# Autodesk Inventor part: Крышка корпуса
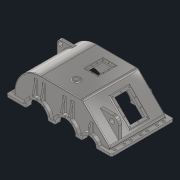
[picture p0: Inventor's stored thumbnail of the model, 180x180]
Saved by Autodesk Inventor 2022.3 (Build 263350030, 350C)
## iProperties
Created: 2022-08
Part Number: Крышка корпуса
Material: Сталь 40ХНМА
Document SubType Name: Modeling
Designer: Карташов
Density: 7.85 g/cm^3
Appearance: С умеренной полировкой
Author: Карташов
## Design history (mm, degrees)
sketch "Эскиз1"
  geometry: L1 (0, 0)-(0, 15); L2 (0, 15)-(30, 15); L3 (30, 15)-(30, 30); L4 (200, 200)-(450, 200); L5 (464.142, 194.142)-(624.142, 34.142); L6 (630, 20)-(630, 15); L7 (630, 15)-(660, 15); L8 (660, 15)-(660, 0); L9 (660, 0)-(0, 0); L10 (0, 0)-(660, 0); L11 (660, 0)-(660, 15); L12 (660, 15)-(0, 15); L13 (0, 15)-(0, 0); A1 r 170 centre (200, 30) between (200, 200) and (30, 30); A2 r 20 centre (450, 180) between (464.142, 194.142) and (450, 200); A3 r 20 centre (610, 20) between (630, 20) and (624.142, 34.142); 4 further points
  constraints: 26 end point, 6 point on circle, 6 tangent, 4 parallel, 3 centre point, 3 horizontal, 3 perpendicular, 2 vertical
  dimensions: "d0" = 200 distance between parallel lines of L4 L9; "d1" = 660 distance of L8.end L1.start; "d2" = 30 distance of L6.end L7.end; "d3" = 15 distance of L7.end L8.end; "d4" = 20 radius of A3; "d5" = 20 radius of A2; "d6" = 30 distance of L1.end L2.end; "d7" = 15 distance of L1.start L1.end; "d8" = 170 radius of A1; "d9" = 45 deg angle of L4 L5; "d10" = 5 distance of L6.start L6.end
extrude "Выдавливание1" new body sketch "Эскиз1" stored distance "d11" = 350; taper "d12" = 0 deg
extrude "Выдавливание2" join sketch "Эскиз1" stored distance "d13" = 390; taper "d14" = 0 deg
feature "Оболочка1" dims "d16" = 15
fillet "Сопряжение2" dims "d17" = 3
sketch "Эскиз2"
  geometry: L1 (660, 15)-(0, 15) reference; L2 (0, 15)-(0, 0) reference; L3 (0, 0)-(660, 0) reference; L4 (660, 0)-(660, 15) reference; L5 (30, 30)-(30, 18) reference; L6 (27, 15)-(630, 15) reference; L7 (630, 15)-(630, 20) reference; L8 (624.142, 34.142)-(464.142, 194.142) reference; L9 (450, 200)-(200, 200) reference; L10 (615, 0)-(45, 0) reference; C1 r 70 at (192, 0); C2 r 65 at (370, 0); C3 r 45 at (520, 0); A1 r 3 centre (27, 18) between (27, 15) and (30, 18) reference; A2 r 20 centre (610, 20) between (630, 20) and (624.142, 34.142) reference; A3 r 20 centre (450, 180) between (464.142, 194.142) and (450, 200) reference; A4 r 170 centre (200, 30) between (200, 200) and (30, 30) reference; 2 further points
  constraints: 3 centre point, 3 point on line, 1 midpoint
  dimensions: "d18" = 140 diameter of C1; "d19" = 130 diameter of C2; "d20" = 90 diameter of C3; "d21" = 192 horizontal distance of point (0, 7.5) C1.centre; "d22" = 178 distance of C2.centre C1.centre; "d23" = 150 distance of C3.centre C2.centre
extrude "Выдавливание3" cut sketch "Эскиз2" distance "d24" = 264.25; taper "d25" = 0 deg
sketch "Эскиз3"
  geometry: L1 (0, 15)-(-660, 15) reference; L2 (-660, 15)-(-660, 0) reference; L3 (-660, 0)-(0, 0) reference; L4 (0, 0)-(0, 15) reference; L5 (-615, 0)-(-45, 0) reference; L6 (-435, 0)-(-475, 0) reference; L7 (-262, 0)-(-305, 0) reference; L8 (-45, 0)-(-122, 0) reference; L9 (-45, 30)-(-45, 0) reference; L10 (-450, 185)-(-200, 185) reference; L11 (-613.536, 23.536)-(-453.536, 183.536) reference; L12 (-615, 0)-(-615, 20) reference; L13 (-565, 0)-(-615, 0) reference; C1 r 75 at (-192, 0); C2 r 55 at (-370, 0); C3 r 45 at (-520, 0); A1 r 45 centre (-520, 0) between (-475, 0) and (-565, 0) reference; A2 r 65 centre (-370, 0) between (-305, 0) and (-435, 0) reference; A3 r 70 centre (-192, 0) between (-122, 0) and (-262, 0) reference; A4 r 155 centre (-200, 30) between (-45, 30) and (-200, 185) reference; A5 r 5 centre (-450, 180) between (-450, 185) and (-453.536, 183.536) reference; A6 r 5 centre (-610, 20) between (-613.536, 23.536) and (-615, 20) reference; 1 further point
  constraints: 3 centre point, 3 coincident, 3 point on line, 2 other
  dimensions: "d26" = 150 diameter of C1; "d27" = 110 diameter of C2; "d28" = 90 diameter of C3
extrude "Выдавливание4" cut sketch "Эскиз3" distance "d29" = 139.5; taper "d30" = 0 deg
sketch "Эскиз4"
  geometry: L1 (306.754, 15)-(260.374, 15) reference; L2 (262, 0)-(305, 0) reference; L3 (562.426, 15)-(630, 15) reference; L4 (630, 15)-(630, 20) reference; L5 (624.142, 34.142)-(464.142, 194.142) reference; L6 (450, 200)-(200, 200) reference; L7 (30, 30)-(30, 18) reference; L8 (27, 15)-(123.626, 15) reference; L9 (260.374, 15)-(306.754, 15) reference; L10 (433.246, 15)-(477.574, 15) reference; C1 r 80 at (370, 0); C2 r 85 at (192, 0); C3 r 60 at (520, 0); A1 r 65 centre (370, 0) between (306.754, 15) and (305, 0) reference; A2 r 70 centre (192, 0) between (262, 0) and (260.374, 15) reference; A3 r 45 centre (520, 0) between (562.426, 15) and (477.574, 15) reference; A4 r 20 centre (610, 20) between (630, 20) and (624.142, 34.142) reference; A5 r 20 centre (450, 180) between (464.142, 194.142) and (450, 200) reference; A6 r 170 centre (200, 30) between (200, 200) and (30, 30) reference; A7 r 3 centre (27, 18) between (27, 15) and (30, 18) reference; A8 r 70 centre (192, 0) between (260.374, 15) and (123.626, 15) reference; A9 r 65 centre (370, 0) between (433.246, 15) and (306.754, 15) reference; 9 further points
  constraints: 3 centre point, 3 coincident
  dimensions: "d31" = 160 diameter of C1; "d32" = 170 diameter of C2; "d33" = 120 diameter of C3
extrude "Выдавливание5" join sketch "Эскиз4" stored distance "d34" = 139.5; taper "d35" = 0 deg
sketch "Эскиз5"
  geometry: L1 (-477.574, 15)-(-422.915, 15) reference; L2 (-317.085, 15)-(-265.485, 15) reference; L3 (-118.515, 15)-(-27, 15) reference; L4 (-30, 18)-(-30, 30) reference; L5 (-200, 200)-(-450, 200) reference; L6 (-464.142, 194.142)-(-624.142, 34.142) reference; L7 (-630, 20)-(-630, 15) reference; L8 (-630, 15)-(-562.426, 15) reference; C1 r 70 at (-370, 0); C2 r 60 at (-520, 0); C3 r 90 at (-192, 0); A1 r 45 centre (-520, 0) between (-477.574, 15) and (-562.426, 15) reference; A2 r 55 centre (-370, 0) between (-317.085, 15) and (-422.915, 15) reference; A3 r 75 centre (-192, 0) between (-118.515, 15) and (-265.485, 15) reference; A4 r 3 centre (-27, 18) between (-30, 18) and (-27, 15) reference; A5 r 170 centre (-200, 30) between (-30, 30) and (-200, 200) reference; A6 r 20 centre (-450, 180) between (-450, 200) and (-464.142, 194.142) reference; A7 r 20 centre (-610, 20) between (-624.142, 34.142) and (-630, 20) reference; 7 further points
  constraints: 3 centre point, 3 coincident
  dimensions: "d36" = 140 diameter of C1; "d37" = 120 diameter of C2; "d38" = 180 diameter of C3
extrude "Выдавливание6" join sketch "Эскиз5" stored distance "d39" = 10; taper "d40" = 0 deg
node "РабПлоскость1"
sketch "Эскиз6"
  geometry: L1 (-130.179, 185)-(-50, 185); L2 (-30, 165)-(-30, 30); L3 (0, 0)-(-122, 0) reference; C1 r 15 at (-50, 165); A1 r 170 centre (-200, 30) between (-30, 30) and (-200, 200) reference; A2 r 20 centre (-50, 165) between (-30, 165) and (-50, 185); 1 further point
  constraints: 4 end point, 4 point on circle, 3 tangent, 2 centre point, 1 coincident, 1 horizontal, 1 midpoint, 1 perpendicular
  dimensions: "d42" = 20 radius of A2; "d43" = 185 distance from line of point (-61, 0) L1; "d44" = 30 diameter of C1
extrude "Выдавливание7" join sketch "Эскиз6" distance "d45" = 20; taper "d46" = 0 deg
fillet "Сопряжение3" dims "d47" = 5
node "РабПлоскость2"
sketch "Эскиз7"
  geometry: L1 (624.142, 34.142)-(464.142, 194.142) reference; L2 (464.142, 194.142)-(624.142, 34.142) reference; L3 (508.284, 150)-(584.142, 150); L4 (624.142, 110)-(624.142, 34.142); L5 (565, 0)-(660, 0) reference; C1 r 15 at (582.272, 116.45); A1 r 20 centre (610, 20) between (630, 20) and (624.142, 34.142) reference; A2 r 40 centre (584.142, 110) between (624.142, 110) and (584.142, 150); 2 further points
  constraints: 4 end point, 2 centre point, 2 point on circle, 2 tangent, 1 horizontal, 1 point on line, 1 vertical
  dimensions: "d50" = 30 diameter of C1; "d51" = 150 distance between parallel lines of L5 L3; "d53" = 33.55 distance from line of L3 C1.centre; "d60" = 40 radius of A2; "d61" = 41.87 distance from line of L4 C1.centre
extrude "Выдавливание8" join sketch "Эскиз7" distance "d54" = 20; taper "d55" = 0 deg
sketch "Эскиз8"
  geometry: L1 (0, 350)-(0, 0) reference; L2 (250, 0)-(0, 0) reference; L3 (250, 350)-(250, 0) reference; L4 (0, 350)-(250, 350) reference; L5 (-200, 370)-(-200, -20) reference; L6 (-91.666, -20)-(75.666, -20) reference; C1 r 20 at (130, 90.38); C2 r 12.5 at (130, 90.38); 1 further point
  constraints: 2 centre point, 1 coincident
  dimensions: "d62" = 40 diameter of C1; "d63" = 25 diameter of C2; "d64" = 330 distance from line of C1.centre L5; "d65" = 110.38 distance from line of C1.centre L6
  node "Спроецированная петля8"
extrude "Выдавливание9" join sketch "Эскиз8" distance "d66" = 5; taper "d67" = 0 deg
extrude "Выдавливание10" cut sketch "Эскиз8" distance "d68" = 39; taper "d69" = 0 deg
fillet "Сопряжение4" dims "d70" = 5
sketch "Эскиз9"
  geometry: L1 (565, 0)-(660, 0) reference; L2 (660, 0)-(660, 15) reference; L3 (660, 15)-(578.095, 15) reference; L4 (461.905, 15)-(448.581, 15) reference; L5 (291.419, 15)-(275.666, 15) reference; L6 (108.334, 15)-(0, 15) reference; L7 (0, 15)-(0, 0) reference; L8 (0, 0)-(122, 0) reference; L9 (262, 0)-(305, 0) reference; L10 (435, 0)-(475, 0) reference; L11 (340, 74.162)-(350, 74.162); L12 (350, 74.162)-(350, 165); L13 (350, 165)-(340, 165); L14 (340, 165)-(340, 74.162); L15 (400, 74.162)-(390, 74.162); L16 (390, 74.162)-(390, 165); L17 (390, 165)-(400, 165); L18 (400, 165)-(400, 74.162); L19 (515, 59.791)-(525, 59.791); L20 (525, 59.791)-(525, 110); L21 (525, 110)-(515, 110); L22 (515, 110)-(515, 59.791); L23 (162, 79.53)-(172, 79.53); L24 (172, 79.53)-(172, 170); L25 (172, 170)-(162, 170); L26 (162, 170)-(162, 79.53); L27 (222, 79.53)-(212, 79.53); L28 (212, 79.53)-(212, 170); L29 (212, 170)-(222, 170); L30 (222, 170)-(222, 79.53); A1 r 45 centre (520, 0) between (565, 0) and (475, 0) reference; A2 r 60 centre (520, 0) between (578.095, 15) and (461.905, 15) reference; A3 r 80 centre (370, 0) between (448.581, 15) and (291.419, 15) reference; A4 r 85 centre (192, 0) between (275.666, 15) and (108.334, 15) reference; A5 r 70 centre (192, 0) between (262, 0) and (122, 0) reference; A6 r 65 centre (370, 0) between (435, 0) and (305, 0) reference; A7 r 85 centre (192, 0) between (275.666, 15) and (108.334, 15) reference; A8 r 80 centre (370, 0) between (448.581, 15) and (291.419, 15) reference; A9 r 60 centre (520, 0) between (578.095, 15) and (461.905, 15) reference; 4 further points
  constraints: 40 end point, 10 parallel, 6 point on circle, 5 horizontal, 5 perpendicular, 4 horizontal alignment, 3 midpoint, 1 point on line
  dimensions: "d72" = 10 distance of L13.end L12.end; "d73" = 10 distance of L16.end L17.end; "d74" = 10 distance of L21.end L20.end; "d75" = 40 distance between parallel lines of L16 L12; "d76" = 10 distance of L25.end L24.end; "d77" = 10 distance of L28.end L29.end; "d78" = 40 distance between parallel lines of L24 L28; "d79" = 170 distance from line of L8 L24.end; "d80" = 5 vertical distance of point (217, 170) point (345, 165); "d81" = 110 distance from line of L1 L20.end
extrude "Выдавливание11" join sketch "Эскиз9" stored distance "d82" = 39; taper "d83" = 0 deg
sketch "Эскиз10"
  geometry: L1 (-117, 0)-(0, 0) reference; L2 (0, 0)-(0, 15) reference; L3 (0, 15)-(-103.259, 15) reference; L4 (-280.741, 15)-(-301.626, 15) reference; L5 (-438.374, 15)-(-461.905, 15) reference; L6 (-578.095, 15)-(-660, 15) reference; L7 (-660, 15)-(-660, 0) reference; L8 (-660, 0)-(-565, 0) reference; L9 (-475, 0)-(-425, 0) reference; L10 (-315, 0)-(-267, 0) reference; L11 (-340, 74.162)-(-340, 165) reference; L12 (-340, 165)-(-350, 165) reference; L13 (-350, 165)-(-350, 77.46) reference; L14 (-390, 77.46)-(-390, 165) reference; L15 (-390, 165)-(-400, 165) reference; L16 (-400, 165)-(-400, 74.162) reference; L17 (-448.581, 15)-(-461.905, 15) reference; L18 (-515, 59.791)-(-515, 110) reference; L19 (-515, 110)-(-525, 110) reference; L20 (-525, 110)-(-525, 59.791) reference; L21 (-578.095, 15)-(-630, 15) reference; L22 (-630, 15)-(-630, 20) reference; L23 (-624.142, 34.142)-(-464.142, 194.142) reference; L24 (-450, 200)-(-200, 200) reference; L25 (-30, 30)-(-30, 18) reference; L26 (-27, 15)-(-108.334, 15) reference; L27 (-162, 79.53)-(-162, 170) reference; L28 (-162, 170)-(-172, 170) reference; L29 (-172, 170)-(-172, 82.614) reference; L30 (-212, 82.614)-(-212, 170) reference; L31 (-212, 170)-(-222, 170) reference; L32 (-222, 170)-(-222, 79.53) reference; L33 (-275.666, 15)-(-291.419, 15) reference; L34 (-400, 165)-(-390, 165); L35 (-390, 165)-(-390, 62.623); L36 (-390, 62.623)-(-400, 62.623); L37 (-400, 62.623)-(-400, 165); L38 (-340, 165)-(-350, 165) reference; L39 (-340, 165)-(-350, 165); L40 (-350, 165)-(-350, 59.748); L41 (-350, 59.748)-(-340, 59.748); L42 (-340, 59.748)-(-340, 165); A1 r 75 centre (-192, 0) between (-117, 0) and (-267, 0) reference; A2 r 90 centre (-192, 0) between (-103.259, 15) and (-280.741, 15) reference; A3 r 70 centre (-370, 0) between (-301.626, 15) and (-438.374, 15) reference; A4 r 60 centre (-520, 0) between (-461.905, 15) and (-578.095, 15) reference; A5 r 45 centre (-520, 0) between (-475, 0) and (-565, 0) reference; A6 r 55 centre (-370, 0) between (-315, 0) and (-425, 0) reference; A7 r 80 centre (-370, 0) between (-350, 77.46) and (-390, 77.46) reference; A8 r 80 centre (-370, 0) between (-400, 74.162) and (-448.581, 15) reference; A9 r 60 centre (-520, 0) between (-461.905, 15) and (-515, 59.791) reference; A10 r 60 centre (-520, 0) between (-525, 59.791) and (-578.095, 15) reference; A11 r 20 centre (-610, 20) between (-624.142, 34.142) and (-630, 20) reference; A12 r 20 centre (-450, 180) between (-450, 200) and (-464.142, 194.142) reference; A13 r 170 centre (-200, 30) between (-30, 30) and (-200, 200) reference; A14 r 3 centre (-27, 18) between (-30, 18) and (-27, 15) reference; A15 r 85 centre (-192, 0) between (-108.334, 15) and (-162, 79.53) reference; A16 r 85 centre (-192, 0) between (-172, 82.614) and (-212, 82.614) reference; A17 r 85 centre (-192, 0) between (-222, 79.53) and (-275.666, 15) reference; A18 r 80 centre (-370, 0) between (-291.419, 15) and (-340, 74.162) reference; 13 further points
  constraints: 16 end point, 4 parallel, 2 horizontal, 2 perpendicular
  dimensions: "d90" = 10 distance of L40.end L41.end; "d91" = 10 distance of L35.end L36.end
extrude "Выдавливание12" join sketch "Эскиз10" stored distance "d92" = 10; taper "d93" = 0 deg
chamfer "Фаска2" distance "d87" = 20; stored, may be unused: second distance "d88" = 2, angle "d89" = 14 deg
chamfer "Фаска1" distance "d84" = 80; stored, may be unused: second distance "d85" = 2, angle "d86" = 14 deg
chamfer "Фаска3" distance "d94" = 80; stored, may be unused: second distance "d95" = 2, angle "d96" = 14 deg
chamfer "Фаска4" distance "d97" = 24; stored, may be unused: second distance "d98" = 2, angle "d99" = 14 deg
fillet "Сопряжение5" dims "d100" = 5
fillet "Сопряжение6" dims "d101" = 5
sketch "Эскиз11"
  geometry: L1 (-62.426, 270)-(-226.274, 270) reference; L2 (-226.274, 0)-(-226.274, 270) reference; L3 (0, 0)-(-226.274, 0) reference; L4 (0, 0)-(0, 350) reference; L5 (-226.274, 350)-(0, 350) reference; L6 (-226.274, 290)-(-226.274, 350) reference; L7 (-226.274, 290)-(-62.426, 290) reference; L8 (-62.426, 290)-(-62.426, 270) reference; L9 (-208.365, 210.91)-(-38.365, 210.91); L10 (-38.365, 210.91)-(-38.365, 90.91); L11 (-38.365, 90.91)-(-208.365, 90.91); L12 (-208.365, 90.91)-(-208.365, 210.91); L13 (-208.365, 210.91)-(-38.365, 90.91); L14 (-38.365, 210.91)-(-208.365, 90.91); L15 (-265.165, 370)-(-265.165, -20) reference; L16 (-193.365, 195.91)-(-53.365, 195.91); L17 (-53.365, 195.91)-(-53.365, 105.91); L18 (-53.365, 105.91)-(-193.365, 105.91); L19 (-193.365, 105.91)-(-193.365, 195.91); L20 (-193.365, 195.91)-(-53.365, 105.91); L21 (-53.365, 195.91)-(-193.365, 105.91); L22 (-200.365, 202.91)-(-46.365, 202.91); L23 (-46.365, 202.91)-(-46.365, 98.91); L24 (-46.365, 98.91)-(-200.365, 98.91); L25 (-200.365, 98.91)-(-200.365, 202.91); L26 (-200.365, 202.91)-(-46.365, 98.91); L27 (-46.365, 202.91)-(-200.365, 98.91); 2 further points
  constraints: 36 end point, 6 midpoint, 6 parallel, 3 horizontal, 3 perpendicular
  dimensions: "d102" = 170 distance of L10.end L11.end; "d103" = 120 distance of L9.end L10.end; "d104" = 90.91 distance between parallel lines of L3 L11; "d105" = 56.8 distance between parallel lines of L12 L15; "d106" = 140 distance of L17.end L18.end; "d107" = 90 distance of L16.end L17.end; "d108" = 154 distance of L23.end L24.end; "d109" = 104 distance of L22.end L23.end
  node "Спроецированная петля12"
extrude "Выдавливание13" join sketch "Эскиз11" distance "d110" = 5; taper "d111" = 0 deg
extrude "Выдавливание14" cut sketch "Эскиз11" distance "d112" = 32.25; taper "d113" = 0 deg
fillet "Сопряжение7" dims "d114" = 5
sketch "Эскиз12"
  geometry: L1 (0, 350)-(0, 0) reference; L2 (250, 0)-(0, 0) reference; L3 (250, 350)-(250, 0) reference; L4 (0, 350)-(250, 350) reference; L5 (90.49, 175)-(180.49, 175); L6 (180.49, 175)-(180.49, 295); L7 (180.49, 295)-(90.49, 295); L8 (90.49, 295)-(90.49, 175); L9 (90.49, 175)-(180.49, 295); L10 (180.49, 175)-(90.49, 295); L11 (140, 370)-(101.626, 370) reference; L12 (-200, 370)-(-200, -20) reference; L13 (102.49, 187)-(168.49, 187); L14 (168.49, 187)-(168.49, 283); L15 (168.49, 283)-(102.49, 283); L16 (102.49, 283)-(102.49, 187); L17 (102.49, 187)-(168.49, 283); L18 (168.49, 187)-(102.49, 283); C1 r 25 at (130, 90.38) reference; 2 further points
  constraints: 24 end point, 4 midpoint, 4 parallel, 2 horizontal, 2 perpendicular
  dimensions: "d115" = 90 distance of L7.end L6.end; "d116" = 120 distance of L6.end L5.end; "d117" = 75 distance between parallel lines of L11 L7; "d118" = 290.49 distance between parallel lines of L12 L8; "d119" = 66 distance of L15.end L14.end; "d120" = 96 distance of L14.end L13.end
  node "Спроецированная петля13"
extrude "Выдавливание15" cut sketch "Эскиз12" distance "d121" = 5; taper "d122" = 0 deg
extrude "Выдавливание16" cut sketch "Эскиз12" distance "d123" = 86.75; taper "d124" = 0 deg
fillet "Сопряжение8" dims "d125" = 10
fillet "Сопряжение9" dims "d126" = 5
fillet "Сопряжение10" dims "d127" = 3
sketch "Эскиз13"
  geometry: L1 (-578.095, 10)-(-578.095, 55) reference; L2 (-578.095, 55)-(-553.095, 55) reference; L3 (-553.095, 55)-(-553.095, 0) reference; L4 (-568.095, 0)-(-553.095, 0) reference; L5 (-578.095, 160)-(-553.095, 160) reference; L6 (-553.095, 160)-(-553.095, 80) reference; L7 (-578.095, 80)-(-553.095, 80) reference; L8 (-578.095, 80)-(-578.095, 160) reference; L9 (-578.095, 260)-(-553.095, 260) reference; L10 (-553.095, 260)-(-553.095, 180) reference; L11 (-578.095, 180)-(-553.095, 180) reference; L12 (-578.095, 180)-(-578.095, 260) reference; L13 (-578.095, 360)-(-553.095, 360) reference; L14 (-553.095, 360)-(-553.095, 280) reference; L15 (-578.095, 280)-(-553.095, 280) reference; L16 (-578.095, 280)-(-578.095, 360) reference; L17 (56.905, 0)-(56.905, 55) reference; L18 (56.905, 55)-(81.905, 55) reference; L19 (81.905, 10)-(81.905, 55) reference; L20 (71.905, 0)-(56.905, 0) reference; L21 (81.905, 80)-(56.905, 80) reference; L22 (56.905, 80)-(56.905, 160) reference; L23 (81.905, 160)-(56.905, 160) reference; L24 (81.905, 80)-(81.905, 160) reference; L25 (81.905, 180)-(56.905, 180) reference; L26 (56.905, 180)-(56.905, 260) reference; L27 (81.905, 260)-(56.905, 260) reference; L28 (81.905, 180)-(81.905, 260) reference; L29 (81.905, 280)-(56.905, 280) reference; L30 (56.905, 280)-(56.905, 360) reference; L31 (81.905, 360)-(56.905, 360) reference; L32 (81.905, 280)-(81.905, 360) reference; C1 r 8 at (-563.095, 35) reference; C2 r 8 at (-563.095, 96.5) reference; C3 r 8 at (-563.095, 137.5) reference; C4 r 8 at (-563.095, 199) reference; C5 r 8 at (-563.095, 240) reference; C6 r 8 at (-563.095, 301.5) reference; C7 r 8 at (-563.095, 342.5) reference; C8 r 8 at (66.905, 35) reference; C9 r 8 at (66.905, 96.5) reference; C10 r 8 at (66.905, 137.5) reference; C11 r 8 at (66.905, 199) reference; C12 r 8 at (66.905, 240) reference; C13 r 8 at (66.905, 301.5) reference; C14 r 8 at (66.905, 342.5) reference; A1 r 10 centre (-568.095, 10) between (-578.095, 10) and (-568.095, 0) reference; A2 r 10 centre (71.905, 10) between (71.905, 0) and (81.905, 10) reference; 1 further point
extrude "Выдавливание17" cut sketch "Эскиз13" extent not by distance; stored distance "d128" = 0; taper "d129" = 0 deg
sketch "Эскиз14"
  geometry: L1 (122, 0)-(10, 0) reference; L2 (10, 0)-(10, -15) reference; L3 (10, -15)-(25, -15) reference; L4 (30, -20)-(30, -180) reference; L5 (30, -180)-(45, -180) reference; L6 (45, -20)-(45, -180) reference; L7 (108.334, -15)-(50, -15) reference; L8 (291.419, -15)-(275.666, -15) reference; L9 (461.905, -15)-(448.581, -15) reference; L10 (610, -15)-(578.095, -15) reference; L11 (615, -180)-(615, -20) reference; L12 (615, -180)-(630, -180) reference; L13 (630, -180)-(630, -20) reference; L14 (650, -15)-(635, -15) reference; L15 (650, -15)-(650, 0) reference; L16 (650, 0)-(565, 0) reference; L17 (475, 0)-(435, 0) reference; L18 (305, 0)-(262, 0) reference; L19 (108.334, 15)-(50, 15); L20 (610, 15)-(578.095, 15); L21 (615, 180)-(615, 20); L22 (291.419, 15)-(275.666, 15); L23 (461.905, 15)-(448.581, 15); C1 r 4 at (474.534, -26.25) reference; C2 r 4 at (565.466, -26.25) reference; C3 r 4 at (520, -52.5) reference; C4 r 4 at (412.614, -58.654) reference; C5 r 4 at (438.952, -22.404) reference; C6 r 4 at (301.048, -22.404) reference; C7 r 4 at (327.386, -58.654) reference; C8 r 4 at (370, -72.5) reference; C9 r 4 at (237.553, -62.699) reference; C10 r 4 at (265.707, -23.949) reference; C11 r 4 at (118.293, -23.949) reference; C12 r 4 at (146.447, -62.699) reference; C13 r 4 at (192, -77.5) reference; C14 r 4 at (118.293, 23.949); C15 r 4 at (146.447, 62.699); C16 r 4 at (192, 77.5); C17 r 4 at (237.553, 62.699); C18 r 4 at (565.466, 26.25); C19 r 4 at (520, 52.5); C20 r 4 at (301.048, 22.404); C21 r 4 at (327.386, 58.654); C22 r 4 at (265.707, 23.949); C23 r 4 at (474.534, 26.25); C24 r 4 at (438.952, 22.404); C25 r 4 at (412.614, 58.654); C26 r 4 at (370, 72.5); A1 r 5 centre (25, -20) between (30, -20) and (25, -15) reference; A2 r 5 centre (50, -20) between (50, -15) and (45, -20) reference; A3 r 85 centre (192, 0) between (108.334, -15) and (162, -79.53) reference; A4 r 85 centre (192, 0) between (162, -79.53) and (172, -82.614) reference; A5 r 85 centre (192, 0) between (172, -82.614) and (212, -82.614) reference; A6 r 85 centre (192, 0) between (212, -82.614) and (222, -79.53) reference; A7 r 85 centre (192, 0) between (222, -79.53) and (275.666, -15) reference; A8 r 80 centre (370, 0) between (291.419, -15) and (340, -74.162) reference; A9 r 80 centre (370, 0) between (340, -74.162) and (350, -77.46) reference; A10 r 80 centre (370, 0) between (350, -77.46) and (390, -77.46) reference; A11 r 80 centre (370, 0) between (390, -77.46) and (400, -74.162) reference; A12 r 80 centre (370, 0) between (400, -74.162) and (448.581, -15) reference; A13 r 60 centre (520, 0) between (461.905, -15) and (490, -51.962) reference; A14 r 60 centre (520, 0) between (490, -51.962) and (500, -56.569) reference; A15 r 60 centre (520, 0) between (500, -56.569) and (540, -56.569) reference; A16 r 60 centre (520, 0) between (540, -56.569) and (550, -51.962) reference; A17 r 60 centre (520, 0) between (550, -51.962) and (578.095, -15) reference; A18 r 5 centre (610, -20) between (615, -20) and (610, -15) reference; A19 r 5 centre (635, -20) between (635, -15) and (630, -20) reference; A20 r 45 centre (520, 0) between (475, 0) and (565, 0) reference; A21 r 65 centre (370, 0) between (305, 0) and (435, 0) reference; A22 r 70 centre (192, 0) between (122, 0) and (262, 0) reference; A23 r 5 centre (50, 20) between (45, 20) and (50, 15); A24 r 85 centre (192, 0) between (162, 79.53) and (108.334, 15); A25 r 85 centre (192, 0) between (172, 82.614) and (162, 79.53); A26 r 85 centre (192, 0) between (212, 82.614) and (172, 82.614); A27 r 85 centre (192, 0) between (222, 79.53) and (212, 82.614); A28 r 70 centre (192, 0) between (262, 0) and (122, 0); A29 r 85 centre (192, 0) between (275.666, 15) and (222, 79.53); A30 r 60 centre (520, 0) between (578.095, 15) and (550, 51.962); A31 r 5 centre (610, 20) between (610, 15) and (615, 20); A32 r 60 centre (520, 0) between (490, 51.962) and (461.905, 15); A33 r 60 centre (520, 0) between (500, 56.569) and (490, 51.962); A34 r 60 centre (520, 0) between (550, 51.962) and (540, 56.569); A35 r 60 centre (520, 0) between (540, 56.569) and (500, 56.569); A36 r 45 centre (520, 0) between (565, 0) and (475, 0); A37 r 80 centre (370, 0) between (340, 74.162) and (291.419, 15); A38 r 80 centre (370, 0) between (350, 77.46) and (340, 74.162); A39 r 80 centre (370, 0) between (390, 77.46) and (350, 77.46); A40 r 80 centre (370, 0) between (400, 74.162) and (390, 77.46); A41 r 80 centre (370, 0) between (448.581, 15) and (400, 74.162); A42 r 65 centre (370, 0) between (435, 0) and (305, 0); 1 further point
  constraints: 40 point on circle, 38 symmetric about line, 33 centre point, 10 end point, 33 other
extrude "Выдавливание18" cut sketch "Эскиз14" distance "d130" = 97; taper "d131" = 0 deg
sketch "Эскиз15"
  geometry: L1 (-45, -180)-(-45, -15) reference; L2 (-45, -180)-(-30, -180) reference; L3 (-30, -180)-(-30, -15) reference; L4 (-30, -15)-(-10, -15) reference; L5 (-10, -15)-(-10, 0) reference; L6 (-10, 0)-(-117, 0) reference; L7 (-267, 0)-(-315, 0) reference; L8 (-425, 0)-(-475, 0) reference; L9 (-565, 0)-(-650, 0) reference; L10 (-650, 0)-(-650, -15) reference; L11 (-650, -15)-(-635, -15) reference; L12 (-630, -20)-(-630, -180) reference; L13 (-630, -180)-(-615, -180) reference; L14 (-615, -20)-(-615, -180) reference; L15 (-578.095, -15)-(-610, -15) reference; L16 (-485, -48.734)-(-484.394, -48.734) reference; L17 (-438.374, -15)-(-461.905, -15) reference; L18 (-280.741, -15)-(-301.626, -15) reference; L19 (-45, -15)-(-103.259, -15) reference; L20 (-45, 15)-(-103.259, 15); L21 (-485, 48.734)-(-484.394, 48.734); L22 (-650, 15)-(-635, 15); L23 (-630, 20)-(-630, 180); L24 (-578.095, 15)-(-610, 15); L25 (-615, 20)-(-615, 180); L26 (-438.374, 15)-(-461.905, 15); L27 (-280.741, 15)-(-301.626, 15); C1 r 4 at (-143.508, -66.744) reference; C2 r 4 at (-113.538, -25.494) reference; C3 r 4 at (-270.462, -25.494) reference; C4 r 4 at (-240.492, -66.744) reference; C5 r 4 at (-192, -82.5) reference; C6 r 4 at (-333.263, -50.564) reference; C7 r 4 at (-310.559, -19.314) reference; C8 r 4 at (-429.441, -19.314) reference; C9 r 4 at (-406.737, -50.564) reference; C10 r 4 at (-370, -62.5) reference; C11 r 4 at (-520, -52.5) reference; C12 r 4 at (-474.534, -26.25) reference; C13 r 4 at (-565.466, -26.25) reference; C14 r 4 at (-143.508, 66.744); C15 r 4 at (-113.538, 25.494); C16 r 4 at (-520, 52.5); C17 r 4 at (-474.534, 26.25); C18 r 4 at (-565.466, 26.25); C19 r 4 at (-429.441, 19.314); C20 r 4 at (-406.737, 50.564); C21 r 4 at (-370, 62.5); C22 r 4 at (-333.263, 50.564); C23 r 4 at (-310.559, 19.314); C24 r 4 at (-192, 82.5); C25 r 4 at (-240.492, 66.744); C26 r 4 at (-270.462, 25.494); A1 r 75 centre (-192, 0) between (-267, 0) and (-117, 0) reference; A2 r 55 centre (-370, 0) between (-425, 0) and (-315, 0) reference; A3 r 45 centre (-520, 0) between (-565, 0) and (-475, 0) reference; A4 r 5 centre (-635, -20) between (-630, -20) and (-635, -15) reference; A5 r 5 centre (-610, -20) between (-610, -15) and (-615, -20) reference; A6 r 60 centre (-520, 0) between (-578.095, -15) and (-555, -48.734) reference; A7 r 60 centre (-520, 0) between (-555, -48.734) and (-545, -54.544) reference; A8 r 60 centre (-520, 0) between (-545, -54.544) and (-495, -54.544) reference; A9 r 60 centre (-520, 0) between (-495, -54.544) and (-485, -48.734) reference; A10 r 4.5 centre (-480.5, -50.99) between (-483.256, -47.433) and (-484.394, -48.734) reference; A11 r 60 centre (-520, 0) between (-483.256, -47.433) and (-461.905, -15) reference; A12 r 70 centre (-370, 0) between (-438.374, -15) and (-405, -60.622) reference; A13 r 70 centre (-370, 0) between (-405, -60.622) and (-395, -65.383) reference; A14 r 70 centre (-370, 0) between (-395, -65.383) and (-345, -65.383) reference; A15 r 70 centre (-370, 0) between (-345, -65.383) and (-335, -60.622) reference; A16 r 70 centre (-370, 0) between (-335, -60.622) and (-301.626, -15) reference; A17 r 90 centre (-192, 0) between (-280.741, -15) and (-227, -82.916) reference; A18 r 90 centre (-192, 0) between (-227, -82.916) and (-217, -86.458) reference; A19 r 90 centre (-192, 0) between (-217, -86.458) and (-167, -86.458) reference; A20 r 90 centre (-192, 0) between (-167, -86.458) and (-157, -82.916) reference; A21 r 90 centre (-192, 0) between (-157, -82.916) and (-103.259, -15) reference; A22 r 90 centre (-192, 0) between (-103.259, 15) and (-157, 82.916); A23 r 45 centre (-520, 0) between (-475, 0) and (-565, 0); A24 r 60 centre (-520, 0) between (-495, 54.544) and (-545, 54.544); A25 r 60 centre (-520, 0) between (-485, 48.734) and (-495, 54.544); A26 r 4.5 centre (-480.5, 50.99) between (-484.394, 48.734) and (-483.256, 47.433); A27 r 60 centre (-520, 0) between (-461.905, 15) and (-483.256, 47.433); A28 r 5 centre (-635, 20) between (-635, 15) and (-630, 20); A29 r 60 centre (-520, 0) between (-555, 48.734) and (-578.095, 15); A30 r 5 centre (-610, 20) between (-615, 20) and (-610, 15); A31 r 60 centre (-520, 0) between (-545, 54.544) and (-555, 48.734); A32 r 55 centre (-370, 0) between (-315, 0) and (-425, 0); A33 r 70 centre (-370, 0) between (-405, 60.622) and (-438.374, 15); A34 r 70 centre (-370, 0) between (-395, 65.383) and (-405, 60.622); A35 r 70 centre (-370, 0) between (-345, 65.383) and (-395, 65.383); A36 r 70 centre (-370, 0) between (-335, 60.622) and (-345, 65.383); A37 r 70 centre (-370, 0) between (-301.626, 15) and (-335, 60.622); A38 r 90 centre (-192, 0) between (-157, 82.916) and (-167, 86.458); A39 r 90 centre (-192, 0) between (-167, 86.458) and (-217, 86.458); A40 r 90 centre (-192, 0) between (-217, 86.458) and (-227, 82.916); A41 r 75 centre (-192, 0) between (-117, 0) and (-267, 0); A42 r 90 centre (-192, 0) between (-227, 82.916) and (-280.741, 15); 1 further point
  constraints: 44 symmetric about line, 42 point on circle, 34 centre point, 16 end point, 34 other
extrude "Выдавливание19" cut sketch "Эскиз15" distance "d132" = 97; taper "d133" = 0 deg
sketch "Эскиз16"
  geometry: C1 r 3 at (202.91, 46.365) reference; C2 r 3 at (150.91, 46.365) reference; C3 r 3 at (98.91, 46.365) reference; C4 r 3 at (98.91, 97.7) reference; C5 r 3 at (98.91, 149.03) reference; C6 r 3 at (98.91, 200.365) reference; C7 r 3 at (150.91, 200.365) reference; C8 r 3 at (202.91, 200.365) reference; C9 r 3 at (202.91, 149.03) reference; C10 r 3 at (202.91, 97.7) reference; 1 further point
extrude "Выдавливание20" cut sketch "Эскиз16" distance "d134" = 89; taper "d135" = 0 deg
sketch "Эскиз17"
  geometry: C1 r 3 at (98.49, 183) reference; C2 r 3 at (98.49, 219.165) reference; C3 r 3 at (98.49, 250.835) reference; C4 r 3 at (98.49, 287) reference; C5 r 3 at (135.49, 287) reference; C6 r 3 at (172.49, 287) reference; C7 r 3 at (172.49, 250.835) reference; C8 r 3 at (172.49, 219.165) reference; C9 r 3 at (172.49, 183) reference; C10 r 3 at (135.49, 183) reference; 2 further points
  constraints: 10 centre point, 21 other
extrude "Выдавливание21" cut sketch "Эскиз17" extent not by distance; stored distance "d136" = 0; taper "d137" = 0 deg
node "Твердое тело1"
node "Спроецированная петля1"
node "Спроецированная петля2"
node "Спроецированная петля3"
node "Спроецированная петля4"
node "Спроецированная петля5"
node "Спроецированная петля6"
node "Спроецированная петля7"
node "Спроецированная петля9"
node "Спроецированная петля10"
node "Спроецированная петля11"
node "Ссылка1"
node "Ссылка2"
node "Ссылка3"
node "Ссылка4"
node "Ссылка5"
node "Ссылка6"
node "Ссылка7"
node "Ссылка8"
node "Ссылка9"
node "Ссылка10"
node "Ссылка11"
node "Ссылка12"
node "Ссылка13"
node "Ссылка14"
node "Ссылка15"
node "Ссылка16"
node "Ссылка17"
node "Ссылка18"
node "Ссылка19"
node "Ссылка20"
